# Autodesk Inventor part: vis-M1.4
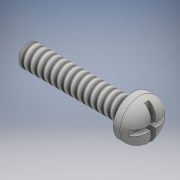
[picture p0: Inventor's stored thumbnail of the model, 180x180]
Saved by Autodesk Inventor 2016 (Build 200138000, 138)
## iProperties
Created: 2018-03
Part Number: vis-M1.4
Material: Générique
Document SubType Name: Modeling
Designer: Bruno
Density: 1 g/cm^3
Appearance: Par défaut
Author: Bruno
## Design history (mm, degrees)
sketch "Esquisse1"
  geometry: C1 r 0.8 at (0, 0); 1 further point
  constraints: 1 centre point, 1 coincident
  dimensions: "d0" = 1.6 diameter of C1
extrude "Extrusion1" new body sketch "Esquisse1" distance "d1" = 8; taper "d2" = 0 deg
sketch "Esquisse2"
  geometry: C1 r 1.5 at (0, 0); 1 further point
  constraints: 1 centre point, 1 coincident
  dimensions: "d3" = 3 diameter of C1
extrude "Extrusion2" join sketch "Esquisse2" distance "d4" = 1.5; taper "d5" = 0 deg
fillet "Congé1" dims "d6" = 1
sketch "Esquisse3"
  geometry: L1 (-0.204, 3.169)-(0.204, 3.169); L2 (0.204, 3.169)-(0.204, -3.51); L3 (0.204, -3.51)-(-0.204, -3.51); L4 (-0.204, -3.51)-(-0.204, 3.169); L5 (-2.999, 0.183)-(3.203, 0.183); L6 (3.203, 0.183)-(3.203, -0.161); L7 (3.203, -0.161)-(-2.999, -0.161); L8 (-2.999, -0.161)-(-2.999, 0.183); 1 further point
  constraints: 16 end point, 4 parallel, 2 horizontal, 2 perpendicular
extrude "Extrusion3" cut sketch "Esquisse3" distance "d7" = 0.5; taper "d8" = 0 deg
chamfer "Chanfrein1" distance "d9" = 0.2; stored, may be unused: second distance "d10" = 2, angle "d11" = 45 deg
feature "Filetage1" dims "d12" = 10, "d13" = 0
node "Solide1"
